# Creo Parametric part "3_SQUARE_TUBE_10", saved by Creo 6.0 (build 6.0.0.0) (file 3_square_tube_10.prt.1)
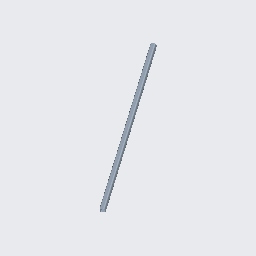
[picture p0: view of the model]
Units: Custom; MM, KILOGRAM, SECS
Materials in the file: STEEL

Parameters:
  BUW_NAME = "SQUARE TUBE"
  BUW_TYPE = "DIN EN 10219"
  BUW_SIZE = "25x25x3.0"
  BUW_LENGTH_STR = "910"
  PTC_MATERIAL_NAME = "STEEL"
  BUW_PROFIL_TYPE = "square_tube"
  BUW_PROFILE_PATH = "parts//profiles/steel_beams_mm/"
  BUW_PROFILE_NAME_LANG = "SQUARE TUBE"
  BUW_TAB_SEL_INFO = "-2 TYPE DIN_EN_10219-1997 SIZE_DINEN_10219 25x25x3.0"
  NAMING = "SQUARE TUBE"
  DESIGNATION = "DIN EN 10219 25x25x3.0 x 910"
  PROFIL_RASTER_POS = "X_0"
  BUW_OBJECT_ROLE = "PROFIL_SYSTEM_BORE_END_POINTS"
  PRO_UNIT_SYS = "Custom"

Other parameters: BUW_LENGTH, LENGTH, BUW_LENGTH_Z_MIN_PARAM, D8, D93, D94, d26, d8, d93, d94, d98, D98, SHEAR_MODULUS, THERM_EXPANSION_REF_TEMPERATURE, STRUCTURAL_DAMPING_COEFFICIENT, STRESS_LIMIT_FOR_TENSION, STRESS_LIMIT_FOR_COMPRESSION, STRESS_LIMIT_FOR_SHEAR, EMISSIVITY

Created from: SQUARE_TUBE.PRT

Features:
  1. datum plane "YZ"
  2. datum plane "XZ"
  3. datum plane "XY"
  4. coordinate system
  5. coordinate system
  6. coordinate system
  7. coordinate system
  8. datum plane "DTM3"
  9. datum plane "DTM4"
  10. datum plane "DTM5"
  11. protrusion
  12. round
  13. round
  14. datum axis
  15. datum point "PNT0"
  16. datum point

Other named items: PROFIL_CUT_QUILT, PROFILE_LENGTH_DIM, CONTACT_SURF_3, CONTACT_SURF_2, CONTACT_SURF_1, CONTACT_SURF_0, E, START_SURFACE, END_SURFACE, SIDE_SURF_3, SIDE_SURF_0, SIDE_SURF_1, SIDE_SURF_2, EDGE_7_S, EDGE_7_E, EDGE_1_S, EDGE_1_E, EDGE_3_S, EDGE_3_E, EDGE_5_S, EDGE_5_E, EDGE_6_S, EDGE_4_S, EDGE_2_S, EDGE_0_S, EDGE_6_E, EDGE_4_E, EDGE_2_E, EDGE_0_E, CS0, CS_S, CS_E, CS3

Named dimensions: X_ROT_S, Y_ROT_S, Z_OFF_S, X_ROT_E, Y_ROT_E, Z_OFF_E, PC_L, BUW_LENGTH_Z_MIN, BUW_LENGTH_DIM

Layers: 00_PROFIL_DATUM, 00_PROFIL_DRW_HIDE, 00_PROFIL_END_CSYS, 00_PROFIL_GEOMETRY, 00_PROFIL_QUILT, 00_PROFIL_SIZE_NOTE

Surfaces: 16 plane, 12 cylinder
